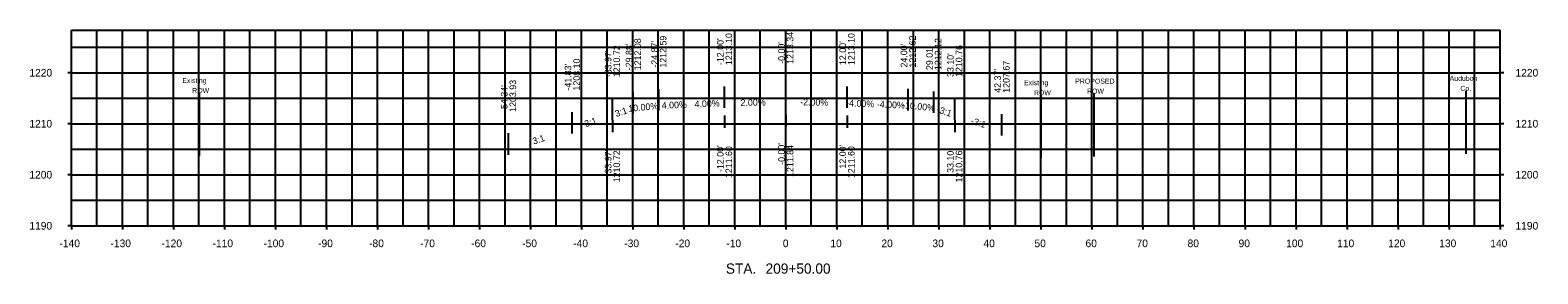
# Model space of a CAD drawing. Extents: x -148 to 147, y 1181 to 1228.
import ezdxf

# ---------------------------------------------------------------- set-up
doc = ezdxf.new("R2010")
doc.units = 0
for name, color, linetype in [('Default', 7, 'Continuous'), ('dsnAlignmentTic', 7, 'Continuous'), ('phoBridge', 7, 'Continuous'), ('phoConcreteSlab', 7, 'Continuous'), ('phoEdgeBank', 7, 'Continuous'), ('phoEdgeCurb', 7, 'Continuous')]:
    doc.layers.add(name, color=color, linetype=linetype)

msp = doc.modelspace()

# ---------------------------------------------------------------- linework, layer by layer
at = {"layer": 'dsnAlignmentTic'}
for p, q in [((-114.98, 1216.02), (-114.98, 1203.71)), ((49.98, 1215.59), (49.98, 1203.28)), ((60.38, 1215.9), (60.38, 1203.59)), ((133.26, 1216.44), (133.26, 1204.13))]:
    msp.add_line(p, q, dxfattribs=at)
at = {"layer": 'phoBridge'}
for p, q in [((-135, 1190), (-135, 1228.35)), ((-125, 1190), (-125, 1228.35)), ((-115, 1190), (-115, 1228.35)), ((-105, 1190), (-105, 1228.35)), ((-95, 1190), (-95, 1228.35)), ((-85, 1190), (-85, 1228.35)), ((-75, 1190), (-75, 1228.35)), ((-65, 1190), (-65, 1228.35)), ((-55, 1190), (-55, 1228.35)), ((-45, 1190), (-45, 1228.35)), ((-35, 1190), (-35, 1228.35)), ((-25, 1190), (-25, 1228.35)), ((-15, 1190), (-15, 1228.35)), ((-5, 1190), (-5, 1228.35)), ((5, 1190), (5, 1228.35)), ((15, 1190), (15, 1228.35)), ((25, 1190), (25, 1228.35)), ((35, 1190), (35, 1228.35)), ((45, 1190), (45, 1228.35)), ((55, 1190), (55, 1228.35)), ((65, 1190), (65, 1228.35)), ((75, 1190), (75, 1228.35)), ((85, 1190), (85, 1228.35)), ((95, 1190), (95, 1228.35)), ((105, 1190), (105, 1228.35)), ((115, 1190), (115, 1228.35)), ((125, 1190), (125, 1228.35)), ((135, 1190), (135, 1228.35)), ((-140, 1225), (140, 1225)), ((-140, 1215), (140, 1215)), ((-140, 1205), (140, 1205)), ((-140, 1195), (140, 1195))]:
    msp.add_line(p, q, dxfattribs=at)
at = {"layer": 'phoConcreteSlab'}
for p, q in [((-12, 1213.1), (-12, 1217.3)), ((-12, 1213.1), (-12, 1217.3)), ((0, 1213.34), (0, 1217.54)), ((0, 1213.34), (0, 1217.54)), ((0, 1213.34), (0, 1217.54)), ((0, 1213.34), (0, 1217.54)), ((12, 1213.1), (12, 1217.3)), ((12, 1213.1), (12, 1217.3)), ((-33.97, 1210.72), (-33.97, 1214.92)), ((-29.88, 1212.08), (-29.88, 1216.28)), ((-24.87, 1212.59), (-24.87, 1216.79)), ((24, 1212.62), (24, 1216.82)), ((29.01, 1212.12), (29.01, 1216.32)), ((33.1, 1210.76), (33.1, 1214.96)), ((33.1, 1210.76), (33.1, 1214.96)), ((-41.83, 1208.1), (-41.83, 1212.3)), ((-12, 1211.6), (-12, 1209.2)), ((0, 1211.84), (0, 1209.44)), ((0, 1211.84), (0, 1209.44)), ((0, 1211.84), (0, 1209.44)), ((12, 1211.6), (12, 1209.2)), ((42.37, 1207.67), (42.37, 1211.87)), ((-33.97, 1210.72), (-33.97, 1208.32)), ((33.1, 1210.76), (33.1, 1208.36)), ((-54.34, 1203.93), (-54.34, 1208.13))]:
    msp.add_line(p, q, dxfattribs=at)
at = {"layer": 'phoEdgeBank'}
for p, q in [((-140, 1228.35), (140, 1228.35)), ((-140, 1190), (-140, 1228.35)), ((140, 1190), (140, 1228.35)), ((-140, 1190), (140, 1190))]:
    msp.add_line(p, q, dxfattribs=at)
at = {"layer": 'phoEdgeCurb'}
for p, q in [((-130, 1190), (-130, 1228.35)), ((-120, 1190), (-120, 1228.35)), ((-110, 1190), (-110, 1228.35)), ((-100, 1190), (-100, 1228.35)), ((-90, 1190), (-90, 1228.35)), ((-80, 1190), (-80, 1228.35)), ((-70, 1190), (-70, 1228.35)), ((-60, 1190), (-60, 1228.35)), ((-50, 1190), (-50, 1228.35)), ((-40, 1190), (-40, 1228.35)), ((-30, 1190), (-30, 1228.35)), ((-20, 1190), (-20, 1228.35)), ((-10, 1190), (-10, 1228.35)), ((0, 1190), (0, 1228.35)), ((10, 1190), (10, 1228.35)), ((20, 1190), (20, 1228.35)), ((30, 1190), (30, 1228.35)), ((40, 1190), (40, 1228.35)), ((50, 1190), (50, 1228.35)), ((60, 1190), (60, 1228.35)), ((70, 1190), (70, 1228.35)), ((80, 1190), (80, 1228.35)), ((90, 1190), (90, 1228.35)), ((100, 1190), (100, 1228.35)), ((110, 1190), (110, 1228.35)), ((120, 1190), (120, 1228.35)), ((130, 1190), (130, 1228.35)), ((-140, 1220), (-140.72, 1220)), ((-140, 1220), (140, 1220)), ((140.72, 1220), (140, 1220)), ((-140, 1210), (-140.72, 1210)), ((-140, 1210), (140, 1210)), ((140.72, 1210), (140, 1210)), ((-140, 1200), (-140.72, 1200)), ((-140, 1200), (140, 1200)), ((140.72, 1200), (140, 1200)), ((-140, 1190), (-140.72, 1190)), ((-140, 1190), (-140, 1189.28)), ((-130, 1190), (-130, 1189.28)), ((-120, 1190), (-120, 1189.28)), ((-110, 1190), (-110, 1189.28)), ((-100, 1190), (-100, 1189.28)), ((-90, 1190), (-90, 1189.28)), ((-80, 1190), (-80, 1189.28)), ((-70, 1190), (-70, 1189.28)), ((-60, 1190), (-60, 1189.28)), ((-50, 1190), (-50, 1189.28)), ((-40, 1190), (-40, 1189.28)), ((-30, 1190), (-30, 1189.28)), ((-20, 1190), (-20, 1189.28)), ((-10, 1190), (-10, 1189.28)), ((0, 1190), (0, 1189.28)), ((10, 1190), (10, 1189.28)), ((20, 1190), (20, 1189.28)), ((30, 1190), (30, 1189.28)), ((40, 1190), (40, 1189.28)), ((50, 1190), (50, 1189.28)), ((60, 1190), (60, 1189.28)), ((70, 1190), (70, 1189.28)), ((80, 1190), (80, 1189.28)), ((90, 1190), (90, 1189.28)), ((100, 1190), (100, 1189.28)), ((110, 1190), (110, 1189.28)), ((120, 1190), (120, 1189.28)), ((130, 1190), (130, 1189.28)), ((140, 1190), (140, 1189.28)), ((140.72, 1190), (140, 1190))]:
    msp.add_line(p, q, dxfattribs=at)

# ---------------------------------------------------------------- texts
at = {"layer": 'Default'}
for s, height, p in [('1220', 1.5, (-148.23, 1219.25)), ('1220', 1.5, (143, 1219.25)), ('1210', 1.5, (-148.23, 1209.25)), ('1210', 1.5, (143, 1209.25)), ('1200', 1.5, (-148.23, 1199.25)), ('1200', 1.5, (143, 1199.25)), ('1190', 1.5, (-148.23, 1189.25)), ('1190', 1.5, (143, 1189.25)), ('-140', 1.5, (-142.33, 1185.8)), ('-130', 1.5, (-132.33, 1185.8)), ('-120', 1.5, (-122.33, 1185.8)), ('-110', 1.5, (-112.33, 1185.8)), ('-100', 1.5, (-102.33, 1185.8)), ('-90', 1.5, (-91.65, 1185.8)), ('-80', 1.5, (-81.65, 1185.8)), ('-70', 1.5, (-71.65, 1185.8)), ('-60', 1.5, (-61.65, 1185.8)), ('-50', 1.5, (-51.65, 1185.8)), ('-40', 1.5, (-41.65, 1185.8)), ('-30', 1.5, (-31.65, 1185.8)), ('-20', 1.5, (-21.65, 1185.8)), ('-10', 1.5, (-11.65, 1185.8)), ('0', 1.5, (-0.58, 1185.8)), ('10', 1.5, (8.74, 1185.8)), ('20', 1.5, (18.74, 1185.8)), ('30', 1.5, (28.74, 1185.8)), ('40', 1.5, (38.74, 1185.8)), ('50', 1.5, (48.74, 1185.8)), ('60', 1.5, (58.74, 1185.8)), ('70', 1.5, (68.74, 1185.8)), ('80', 1.5, (78.74, 1185.8)), ('90', 1.5, (88.74, 1185.8)), ('100', 1.5, (98.06, 1185.8)), ('110', 1.5, (108.06, 1185.8)), ('120', 1.5, (118.06, 1185.8)), ('130', 1.5, (128.06, 1185.8)), ('140', 1.5, (138.06, 1185.8)), ('STA.', 2.004, (-11.74, 1180.6)), ('209+50.00', 2.004, (-3.96, 1180.6))]:
    msp.add_text(s, height=height, dxfattribs=at).set_placement(p)
at = {"layer": 'dsnAlignmentTic'}
for s, p in [('Existing', (-118.26, 1217.98)), ('Existing', (46.7, 1217.55)), ('PROPOSED', (56.73, 1217.86)), ('Audubon', (130.1, 1218.41)), ('Co.', (132.2, 1216.44)), ('ROW', (-116.32, 1216.02)), ('ROW', (48.64, 1215.59)), ('ROW', (59.04, 1215.9))]:
    msp.add_text(s, height=0.984, dxfattribs=at).set_placement(p)
at = {"layer": 'phoConcreteSlab'}
for s, rotation, p in [('1212.08', 90, (-28.39, 1220.48)), ('1212.59', 90, (-23.38, 1220.99)), ("-12.00'", 90, (-12.19, 1221.5)), ("-12.00'", 90, (-12.19, 1221.5)), ('1213.10', 90, (-10.51, 1221.5)), ('1213.10', 90, (-10.51, 1221.5)), ('1213.34', 90, (1.49, 1221.74)), ('1213.34', 90, (1.49, 1221.74)), ('1213.34', 90, (1.49, 1221.74)), ('1213.34', 90, (1.49, 1221.74)), ('1213.10', 90, (13.49, 1221.5)), ('1213.10', 90, (13.49, 1221.5)), ('1212.62', 90, (25.49, 1221.02)), ('1212.12', 90, (30.5, 1220.52)), ("-33.97'", 90, (-34.16, 1219.12)), ('1210.72', 90, (-32.48, 1219.12)), ("-29.88'", 90, (-30.07, 1220.48)), ("-24.87'", 90, (-25.06, 1220.99)), ("-0.00'", 90, (-0.19, 1221.74)), ("-0.00'", 90, (-0.19, 1221.74)), ("-0.00'", 90, (-0.19, 1221.74)), ("-0.00'", 90, (-0.19, 1221.74)), ("12.00'", 90, (11.81, 1221.5)), ("12.00'", 90, (11.81, 1221.5)), ("24.00'", 90, (23.81, 1221.02)), ("29.01'", 90, (28.81, 1220.52)), ("33.10'", 90, (32.9, 1219.16)), ("33.10'", 90, (32.9, 1219.16)), ('1210.76', 90, (34.59, 1219.16)), ('1210.76', 90, (34.59, 1219.16)), ("-41.83'", 90, (-42.03, 1216.5)), ('1208.10', 90, (-40.34, 1216.5)), ("42.37'", 90, (42.17, 1216.07)), ('1207.67', 90, (43.86, 1216.07)), ("-54.34'", 90, (-54.53, 1212.33)), ('1203.93', 90, (-52.84, 1212.33)), ('4.00%', 2.2906, (-24.28, 1212.93)), ('4.00%', 2.2906, (-17.85, 1213.19)), ('2.00%', 1.1458, (-8.85, 1213.48)), ('-2.00%', 358.8542, (2.81, 1213.61)), ('-4.00%', 357.7094, (11.82, 1213.43)), ('-4.00%', 357.7094, (17.82, 1213.19)), ('3:1', 18.4332, (-33.22, 1211.3)), ('10.00%', 5.7106, (-30.79, 1212.31)), ('-10.00%', 354.2894, (22.75, 1213.07)), ('-3:1', 341.5668, (29.45, 1212.29)), ('3:1', 18.4332, (-39.19, 1209.3)), ('-3:1', 341.5668, (36.13, 1210.07)), ('3:1', 18.4332, (-49.38, 1205.91)), ("-12.00'", 90, (-12.19, 1200.53)), ('1211.60', 90, (-10.51, 1199.34)), ("-0.00'", 90, (-0.19, 1201.94)), ("-0.00'", 90, (-0.19, 1201.94)), ("-0.00'", 90, (-0.19, 1201.94)), ('1211.84', 90, (1.49, 1199.56)), ('1211.84', 90, (1.49, 1199.56)), ('1211.84', 90, (1.49, 1199.56)), ("12.00'", 90, (11.81, 1201.21)), ('1211.60', 90, (13.49, 1199.34)), ("-33.97'", 90, (-34.16, 1199.65)), ('1210.72', 90, (-32.48, 1198.52)), ("33.10'", 90, (32.9, 1200.37)), ('1210.76', 90, (34.59, 1198.49))]:
    msp.add_text(s, height=1.296, rotation=rotation, dxfattribs=at).set_placement(p)

doc.saveas('drawing.dxf')
